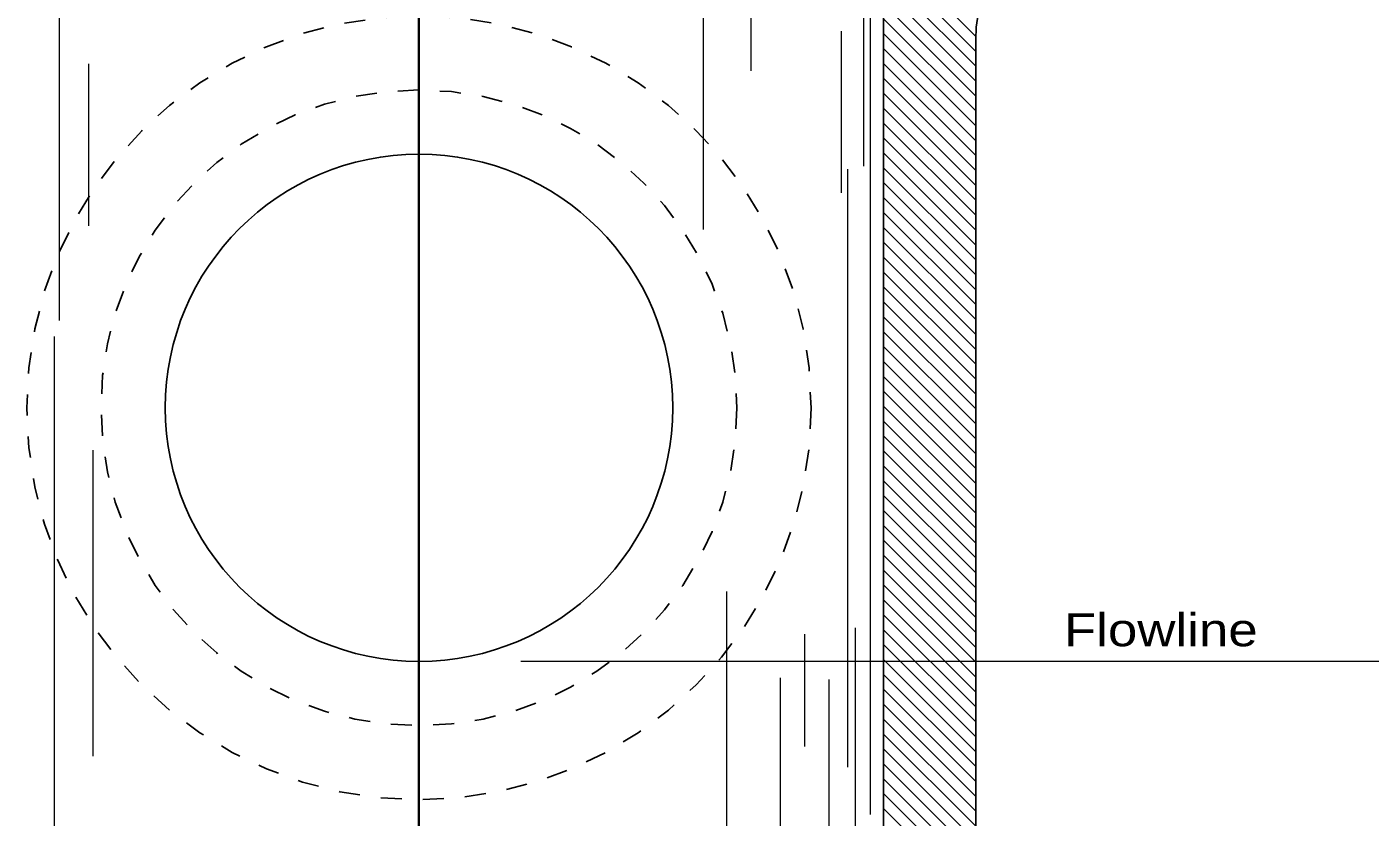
# Model space of a CAD drawing. Extents: x 1302.9 to 1336.9, y 688.5 to 710.5.
# Drawn here: x 1308.08 to 1314.45, y 695.37 to 699.12 of the extents above; entities that cross this region are included whole.
import ezdxf
from ezdxf.enums import TextEntityAlignment as Align

# ---------------------------------------------------------------- set-up
doc = ezdxf.new("R2010")
doc.units = 0
doc.header["$LTSCALE"] = 0.062
doc.linetypes.add('SHORT_DASHED', pattern=[2.7, 1.5, -1.2])
doc.layers.add('1', color=7, linetype='Continuous', lineweight=13)

msp = doc.modelspace()

# ---------------------------------------------------------------- linework, layer by layer
at = {"layer": '1', "lineweight": 35}
msp.add_line((1309.9415, 692.06492), (1309.9415, 702.87), dxfattribs=at)
at = {"layer": '1'}
for p, q in [((1312.04967, 698.46067), (1312.04967, 702.85392)), ((1311.51667, 698.91258), (1311.51667, 701.1255)), ((1308.23617, 699.94242), (1308.23617, 697.7295)), ((1312.08167, 695.38725), (1312.08167, 699.7805)), ((1311.2895, 698.1605), (1311.2895, 699.6055)), ((1312.58108, 699.07633), (1312.14367, 699.51375)), ((1312.58108, 699.00567), (1312.14367, 699.44308)), ((1312.58092, 698.93517), (1312.14367, 699.37242)), ((1312.58092, 698.8645), (1312.14367, 699.30175)), ((1312.58092, 698.79383), (1312.14367, 699.23108)), ((1312.58092, 698.72317), (1312.14367, 699.16042)), ((1311.94208, 699.10142), (1311.94208, 698.33425)), ((1312.58092, 698.6525), (1312.14367, 699.08975)), ((1312.58092, 698.58183), (1312.14367, 699.01908)), ((1308.37633, 698.17858), (1308.37633, 698.94575)), ((1312.58092, 698.51117), (1312.14367, 698.94842)), ((1312.58092, 698.4405), (1312.14367, 698.87775)), ((1312.58092, 698.36983), (1312.14367, 698.80708)), ((1312.58092, 698.29917), (1312.14367, 698.73642)), ((1312.58092, 698.2285), (1312.14367, 698.66575)), ((1312.58092, 698.15775), (1312.14367, 698.595)), ((1312.58092, 698.08717), (1312.14367, 698.52442)), ((1311.972, 698.44625), (1311.972, 695.61117)), ((1312.58092, 698.01642), (1312.14367, 698.45367)), ((1312.58092, 697.94583), (1312.14367, 698.383)), ((1312.58092, 697.87508), (1312.14367, 698.31233)), ((1312.58092, 697.8045), (1312.14367, 698.24167)), ((1312.58092, 697.73375), (1312.14367, 698.171)), ((1312.58092, 697.66308), (1312.14367, 698.10033)), ((1312.58092, 697.59242), (1312.14367, 698.02967)), ((1312.58092, 697.52175), (1312.14367, 697.959)), ((1312.58092, 697.45108), (1312.14367, 697.88833)), ((1312.58092, 697.38042), (1312.14367, 697.81767)), ((1312.58092, 697.30975), (1312.14367, 697.747)), ((1312.58092, 697.23908), (1312.14367, 697.67633)), ((1308.21275, 697.65342), (1308.21275, 693.26017)), ((1312.58092, 697.16842), (1312.14367, 697.60567)), ((1312.58092, 697.09775), (1312.14367, 697.535)), ((1312.58092, 697.02708), (1312.14367, 697.46433)), ((1312.58092, 696.95642), (1312.14367, 697.39367)), ((1312.58092, 696.88575), (1312.14367, 697.323)), ((1312.58092, 696.815), (1312.14367, 697.25225)), ((1312.58092, 696.74442), (1312.14367, 697.18167)), ((1308.396, 697.11442), (1308.396, 695.6625)), ((1312.58092, 696.67367), (1312.14367, 697.11092)), ((1312.58092, 696.60308), (1312.14367, 697.04033)), ((1312.58092, 696.53233), (1312.14367, 696.96958)), ((1312.58092, 696.46175), (1312.14367, 696.899)), ((1312.58092, 696.391), (1312.14367, 696.82825)), ((1312.58092, 696.32042), (1312.14367, 696.75767)), ((1312.58092, 696.24967), (1312.14367, 696.68692)), ((1312.58092, 696.17908), (1312.14367, 696.61633)), ((1312.58092, 696.10833), (1312.14367, 696.54558)), ((1311.40092, 693.50458), (1311.40092, 696.44417)), ((1312.58092, 696.03775), (1312.14367, 696.475)), ((1312.58092, 695.967), (1312.14367, 696.40425)), ((1312.58092, 695.89642), (1312.14367, 696.33367)), ((1312.00975, 693.20825), (1312.00975, 696.27125)), ((1312.58092, 695.82567), (1312.14367, 696.26292)), ((1311.77025, 695.70875), (1311.77025, 696.24208)), ((1312.58092, 695.75508), (1312.14367, 696.19233)), ((1315.92042, 696.11292), (1310.42467, 696.11292)), ((1312.58092, 695.68433), (1312.14367, 696.12158)), ((1311.65292, 696.03525), (1311.65292, 693.91133)), ((1311.88633, 693.23183), (1311.88633, 696.02642)), ((1312.58092, 695.61367), (1312.14367, 696.05092)), ((1312.58092, 695.543), (1312.14367, 695.98025)), ((1312.58092, 695.47233), (1312.14367, 695.90958)), ((1312.58092, 695.40167), (1312.14367, 695.83892)), ((1312.58092, 695.331), (1312.14367, 695.76825)), ((1312.58092, 695.26033), (1312.14367, 695.69758)), ((1312.58092, 695.18967), (1312.14367, 695.62692)), ((1312.58092, 695.119), (1312.14367, 695.55625)), ((1312.58092, 695.04833), (1312.14367, 695.48558)), ((1312.58092, 694.97767), (1312.14367, 695.41492))]:
    msp.add_line(p, q, dxfattribs=at)
at = {"layer": '1', "lineweight": 25}
for p, q in [((1312.58108, 698.95525), (1312.58108, 699.08017)), ((1312.58092, 692.86483), (1312.58092, 698.95525))]:
    msp.add_line(p, q, dxfattribs=at)
msp.add_lwpolyline([(1312.92967, 700.76658), (1312.73708, 700.04825), (1312.58092, 700.04825), (1312.14367, 700.04825), (1312.14367, 692.86483), (1312.58092, 692.86483)], dxfattribs=at)
msp.add_ellipse((1313.04962, 699.08014), major_axis=(0.46853, 0), ratio=0.999895, start_param=2.4506156, end_param=3.1415927, dxfattribs=at)
at = {"layer": '1', "linetype": 'SHORT_DASHED', "lineweight": 25}
for major_axis in [(1.85854, 0), (1.50721, 0)]:
    msp.add_ellipse((1309.9415, 697.31541), major_axis=major_axis, ratio=0.999895, dxfattribs=at)
at = {"layer": '1', "lineweight": 25}
msp.add_ellipse((1309.9415, 697.31541), major_axis=(1.2026, 0), ratio=0.999895, dxfattribs=at)

# ---------------------------------------------------------------- texts
at = {"layer": '1', "width": 1.2}
msp.add_text('Flowline', height=0.156, dxfattribs=at).set_placement((1313.45742, 696.1845), align=Align.CENTER)

doc.saveas('drawing.dxf')
